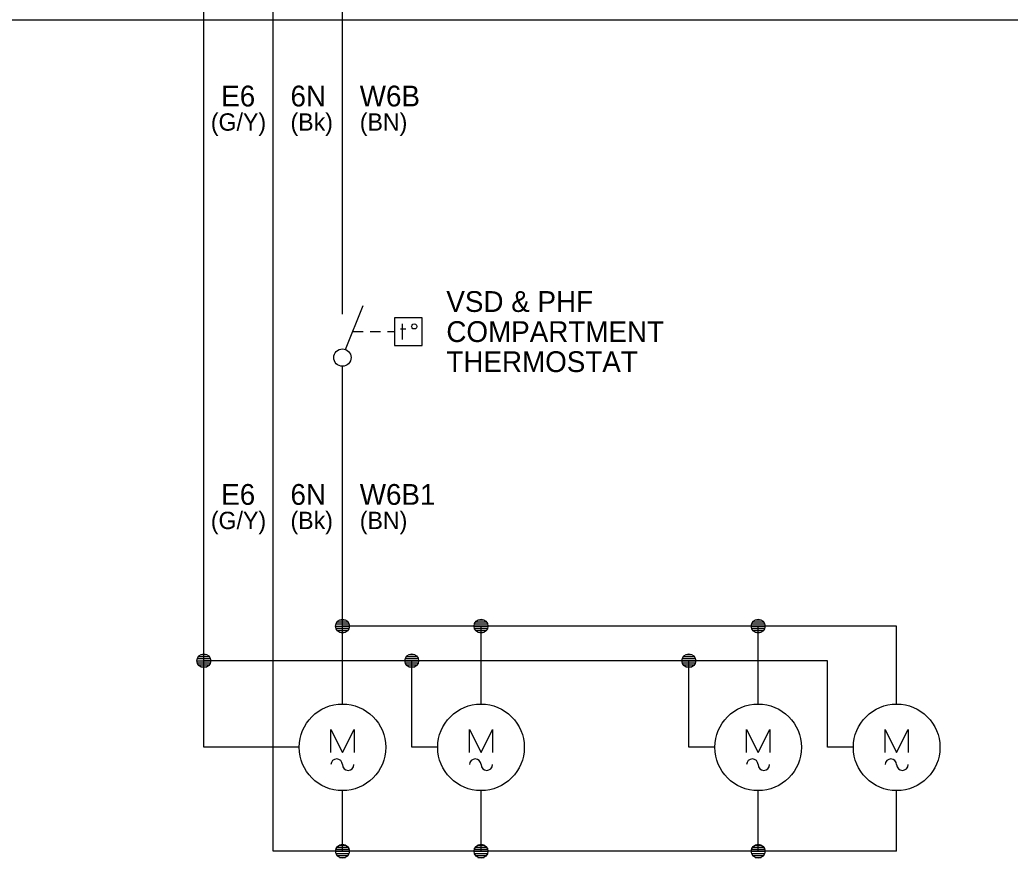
# Model space of a CAD drawing. Extents: x 0 to 841, y 0 to 594.
# Drawn here: x 493.4 to 636.4, y 119 to 240 of the extents above; entities that cross this region are included whole.
import ezdxf

# ---------------------------------------------------------------- set-up
doc = ezdxf.new("R2010")
doc.units = 0
doc.layers.add('Level 1', color=7, linetype='Continuous')
doc.layers.add('Level 10', color=7, linetype='Continuous')

msp = doc.modelspace()

# ---------------------------------------------------------------- linework, layer by layer
at = {"layer": 'Level 1'}
for p, q in [((540, 200), (540, 418.75)), ((530, 120), (530, 408.75)), ((520, 135), (520, 398.75)), ((28, 240), (829, 240)), ((540, 197.5), (540, 200)), ((540.46, 192.41), (543, 198.75)), ((541.5, 195), (543, 195)), ((544, 195), (545.5, 195)), ((546.5, 195), (547.5, 195)), ((540, 141.25), (540, 190)), ((620, 152.5), (540, 152.5)), ((560, 141.25), (560, 152.5)), ((600, 141.25), (600, 152.5)), ((620, 141.25), (620, 152.5)), ((610, 147.5), (520, 147.5)), ((550, 135), (550, 147.5)), ((590, 135), (590, 147.5)), ((610, 135), (610, 147.5)), ((533.75, 135), (520, 135)), ((553.75, 135), (550, 135)), ((593.75, 135), (590, 135)), ((613.75, 135), (610, 135)), ((540, 120), (540, 128.75)), ((560, 120), (560, 128.75)), ((600, 120), (600, 128.75)), ((620, 120), (620, 128.75)), ((620, 120), (530, 120))]:
    msp.add_line(p, q, dxfattribs=at)
msp.add_lwpolyline([(547.5, 193), (551.5, 193), (551.5, 197), (547.5, 197)], close=True, dxfattribs=at)
for points in [[(548.63, 196.13), (548.63, 193.87)], [(550.36, 195.38), (550.18, 195.42), (550.05, 195.56), (549.99, 195.76), (550.05, 195.94), (550.18, 196.07), (550.36, 196.13), (550.56, 196.07), (550.7, 195.94), (550.74, 195.76), (550.7, 195.56), (550.56, 195.42), (550.36, 195.38)], [(548.38, 195.38), (549.13, 195.38)]]:
    msp.add_lwpolyline(points, dxfattribs=at)
msp.add_circle((540, 191.25), 1.25, dxfattribs=at)
at = {"layer": 'Level 10'}
for p, q in [((539.2, 153.1), (540.8, 153.1)), ((539.56, 153.4), (540.44, 153.4)), ((540, 153.5), (540, 153.5)), ((559.2, 153.1), (560.8, 153.1)), ((559.56, 153.4), (560.44, 153.4)), ((560, 153.5), (560, 153.5)), ((599.2, 153.1), (600.8, 153.1)), ((599.56, 153.4), (600.44, 153.4)), ((600, 153.5), (600, 153.5)), ((539, 152.5), (540.99, 152.5)), ((539.05, 152.8), (540.95, 152.8)), ((539.05, 152.2), (540.95, 152.2)), ((539.2, 151.9), (540.8, 151.9)), ((539.56, 151.6), (540.44, 151.6)), ((559, 152.5), (560.99, 152.5)), ((559.05, 152.8), (560.95, 152.8)), ((559.05, 152.2), (560.95, 152.2)), ((559.2, 151.9), (560.8, 151.9)), ((559.56, 151.6), (560.44, 151.6)), ((599, 152.5), (600.99, 152.5)), ((599.05, 152.8), (600.95, 152.8)), ((599.05, 152.2), (600.95, 152.2)), ((599.2, 151.9), (600.8, 151.9)), ((599.56, 151.6), (600.44, 151.6)), ((519, 147.5), (520.99, 147.5)), ((519.05, 147.8), (520.95, 147.8)), ((519.2, 148.1), (520.8, 148.1)), ((519.56, 148.4), (520.44, 148.4)), ((520, 148.5), (520, 148.5)), ((549, 147.5), (550.99, 147.5)), ((549.05, 147.8), (550.95, 147.8)), ((549.2, 148.1), (550.8, 148.1)), ((549.56, 148.4), (550.44, 148.4)), ((550, 148.5), (550, 148.5)), ((589, 147.5), (590.99, 147.5)), ((589.05, 147.8), (590.95, 147.8)), ((589.2, 148.1), (590.8, 148.1)), ((589.56, 148.4), (590.44, 148.4)), ((590, 148.5), (590, 148.5)), ((519.05, 147.2), (520.95, 147.2)), ((519.2, 146.9), (520.8, 146.9)), ((519.56, 146.6), (520.44, 146.6)), ((549.05, 147.2), (550.95, 147.2)), ((549.2, 146.9), (550.8, 146.9)), ((549.56, 146.6), (550.44, 146.6)), ((589.05, 147.2), (590.95, 147.2)), ((589.2, 146.9), (590.8, 146.9)), ((589.56, 146.6), (590.44, 146.6)), ((538.33, 137.58), (540, 134.25)), ((538.33, 134.25), (538.33, 137.58)), ((540, 134.25), (541.67, 137.58)), ((541.67, 137.58), (541.67, 134.25)), ((558.33, 137.58), (560, 134.25)), ((558.33, 134.25), (558.33, 137.58)), ((560, 134.25), (561.67, 137.58)), ((561.67, 137.58), (561.67, 134.25)), ((598.33, 137.58), (600, 134.25)), ((598.33, 134.25), (598.33, 137.58)), ((600, 134.25), (601.67, 137.58)), ((601.67, 137.58), (601.67, 134.25)), ((618.33, 137.58), (620, 134.25)), ((618.33, 134.25), (618.33, 137.58)), ((620, 134.25), (621.67, 137.58)), ((621.67, 137.58), (621.67, 134.25)), ((539.05, 120.3), (540.95, 120.3)), ((539.2, 120.6), (540.8, 120.6)), ((539.56, 120.9), (540.44, 120.9)), ((540, 121), (540, 121)), ((559.05, 120.3), (560.95, 120.3)), ((559.2, 120.6), (560.8, 120.6)), ((559.56, 120.9), (560.44, 120.9)), ((560, 121), (560, 121)), ((599.05, 120.3), (600.95, 120.3)), ((599.2, 120.6), (600.8, 120.6)), ((599.56, 120.9), (600.44, 120.9)), ((600, 121), (600, 121)), ((539, 120), (540.99, 120)), ((539.05, 119.7), (540.95, 119.7)), ((539.2, 119.4), (540.8, 119.4)), ((539.56, 119.1), (540.44, 119.1)), ((559, 120), (560.99, 120)), ((559.05, 119.7), (560.95, 119.7)), ((559.2, 119.4), (560.8, 119.4)), ((559.56, 119.1), (560.44, 119.1)), ((599, 120), (600.99, 120)), ((599.05, 119.7), (600.95, 119.7)), ((599.2, 119.4), (600.8, 119.4)), ((599.56, 119.1), (600.44, 119.1))]:
    msp.add_line(p, q, dxfattribs=at)
for centre, radius in [((540, 152.5), 1), ((560, 152.5), 1), ((600, 152.5), 1), ((520, 147.5), 1), ((550, 147.5), 1), ((590, 147.5), 1), ((540, 135), 6.25), ((560, 135), 6.25), ((600, 135), 6.25), ((620, 135), 6.25), ((540, 120), 1), ((560, 120), 1), ((600, 120), 1)]:
    msp.add_circle(centre, radius, dxfattribs=at)
for centre, start, end in [((539.17, 132.5), 0, 180), ((559.17, 132.5), 0, 180), ((599.17, 132.5), 0, 180), ((619.17, 132.5), 0, 180), ((540.83, 132.5), 180, 0), ((560.83, 132.5), 180, 0), ((600.83, 132.5), 180, 0), ((620.83, 132.5), 180, 0)]:
    msp.add_arc(centre, 0.83, start, end, dxfattribs=at)

# ---------------------------------------------------------------- texts
at = {"layer": 'Level 1'}
for s, height, p in [('E6', 3, (522.5, 227.5)), ('6N', 3, (532.5, 227.5)), ('W6B', 3, (542.5, 227.5)), ('(G/Y)', 2.5, (521, 224)), ('(Bk)', 2.5, (532.5, 224)), ('(BN)', 2.5, (542.5, 224)), ('VSD & PHF', 3, (555, 197.84)), ('COMPARTMENT', 3, (555, 193.5)), ('THERMOSTAT', 3, (555, 189.16)), ('E6', 3, (522.5, 170)), ('6N', 3, (532.5, 170)), ('W6B1', 3, (542.5, 170)), ('(G/Y)', 2.5, (521, 166.5)), ('(Bk)', 2.5, (532.5, 166.5)), ('(BN)', 2.5, (542.5, 166.5))]:
    msp.add_text(s, height=height, dxfattribs=at).set_placement(p)

doc.saveas('drawing.dxf')
